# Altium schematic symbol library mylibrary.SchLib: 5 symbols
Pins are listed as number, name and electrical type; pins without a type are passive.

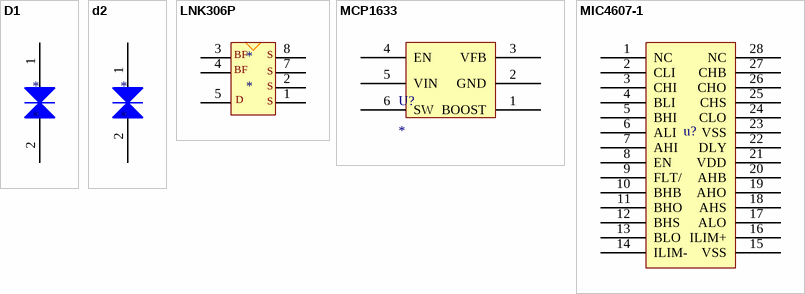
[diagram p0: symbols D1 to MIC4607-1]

## D1
designator *
pins: 1, 2
1 alternate drawing of the same symbol

## d2
designator *
pins: 1, 2

## LNK306P
designator *
pins: 1, 2, 3, 4, 5, 7, 8

## MCP1633
designator U?
pins: 1 BOOST, 2 GND, 3 VFB, 4 EN, 5 VIN, 6 SW

## MIC4607-1
designator u?  (value not drawn)
pins: 1 NC, 2 CLI, 3 CHI, 4 BLI, 5 BHI, 6 ALI, 7 AHI, 8 EN, 9 FLT/, 10 BHB, 11 BHO, 12 BHS, 13 BLO, 14 ILIM-, 15 VSS, 16 ILIM+, 17 ALO, 18 AHS, 19 AHO, 20 AHB, 21 VDD, 22 DLY, 23 VSS, 24 CLO, 25 CHS, 26 CHO, 27 CHB, 28 NC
